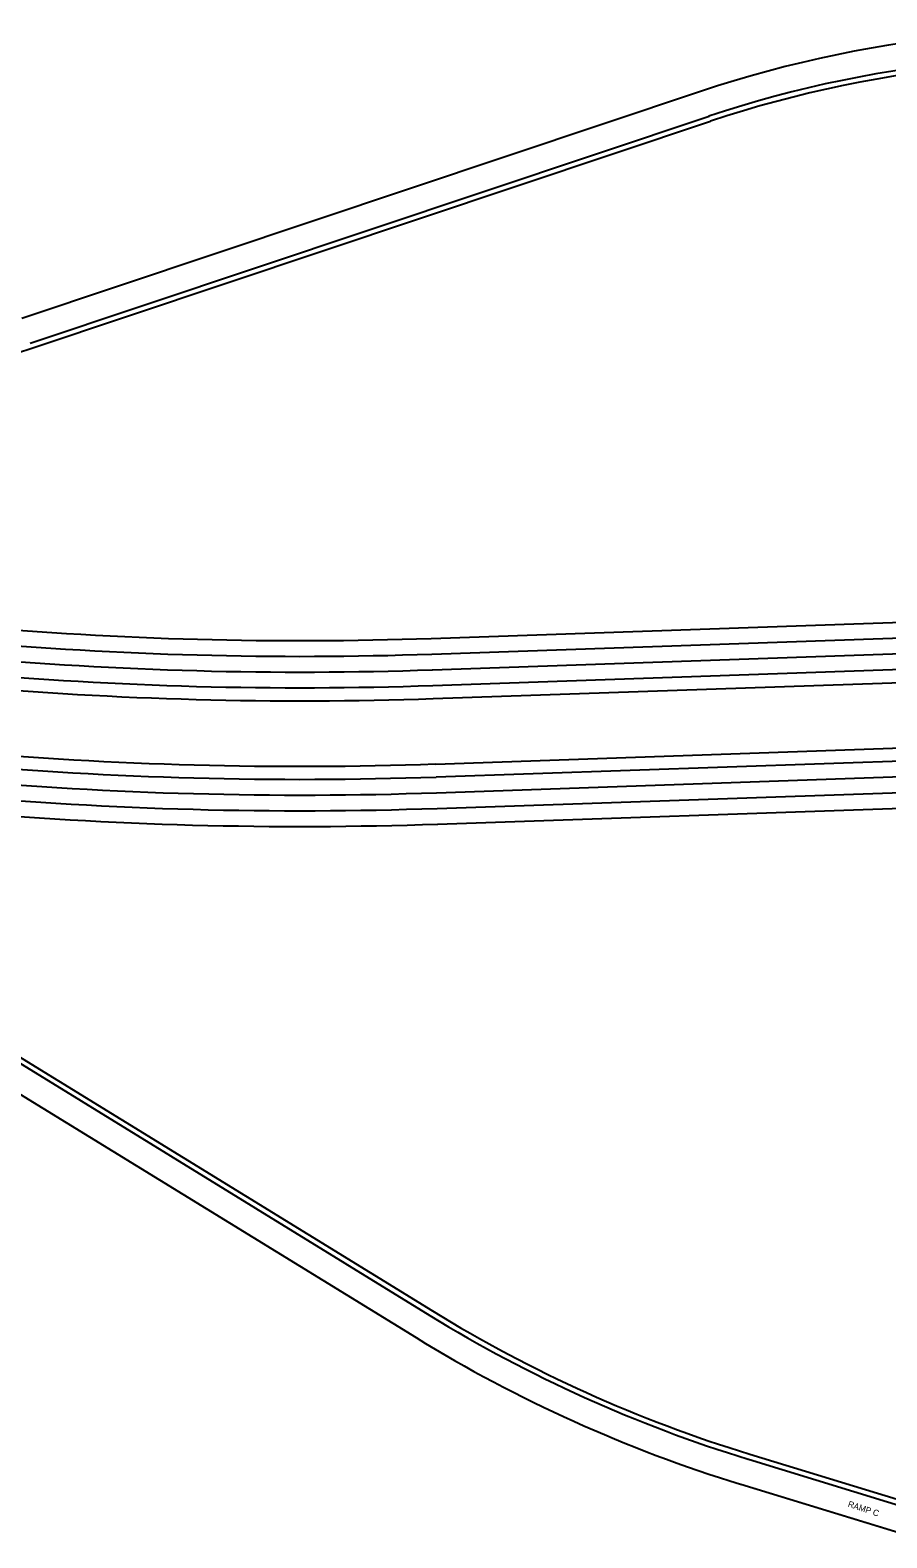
# Model space of a CAD drawing. Extents: x 2315515 to 2326910, y 758186 to 762794.
# Drawn here: x 2319969 to 2320623, y 759595 to 760747 of the extents above; entities that cross this region are included whole.
import ezdxf

# ---------------------------------------------------------------- set-up
doc = ezdxf.new("R2010")
doc.units = 0
for name, color, linetype in [('_CIVIL_CONSTRUCTION', 7, 'Continuous'), ('Default', 7, 'Continuous'), ('Draft_Corr_Design', 7, 'Continuous'), ('Draft_Corr_Range_Design', 7, 'Continuous'), ('E_Terrain_Exterior', 7, 'Continuous'), ('TL_Base Extension Sub', 7, 'Continuous'), ('TL_Pavement Centerline', 7, 'Continuous'), ('TL_Pavement Centerline Sub', 7, 'Continuous')]:
    doc.layers.add(name, color=color, linetype=linetype)

msp = doc.modelspace()

# ---------------------------------------------------------------- linework, layer by layer
at = {"layer": '_CIVIL_CONSTRUCTION'}
for p, q in [((2320276.5, 760246.3), (2324006, 760375.3)), ((2320278.9, 760176.4), (2324008.4, 760305.3))]:
    msp.add_line(p, q, dxfattribs=at)
for radius in [2931, 3001]:
    msp.add_arc((2320175.2, 763175.6), radius, 264.9144, 271.9805, dxfattribs=at)
at = {"layer": 'Draft_Corr_Design'}
for p, q in [((2320276.8, 760236.3), (2324006.3, 760365.3)), ((2320278.5, 760186.3), (2324008.1, 760315.3))]:
    msp.add_line(p, q, dxfattribs=at)
for radius in [2941, 2991]:
    msp.add_arc((2320175.2, 763175.6), radius, 264.9144, 271.9805, dxfattribs=at)
at = {"layer": 'Draft_Corr_Range_Design'}
for p, q in [((2320276.1, 760258.3), (2324005.6, 760387.3)), ((2320279.3, 760164.4), (2324008.8, 760293.3))]:
    msp.add_line(p, q, dxfattribs=at)
for radius in [2919, 3013]:
    msp.add_arc((2320175.2, 763175.6), radius, 264.9144, 271.9805, dxfattribs=at)
at = {"layer": 'E_Terrain_Exterior'}
for p, q in [((2319968.8, 760508), (2320487.5, 760681.4)), ((2319968.8, 760508), (2320487.5, 760681.4)), ((2319848.5, 760026.7), (2320274.1, 759765)), ((2320517.6, 759655.1), (2320668.3, 759608.9))]:
    msp.add_line(p, q, dxfattribs=at)
for centre, radius, start, end in [((2320768.6, 759840.1), 887, 81.2923, 108.4803), ((2320768.6, 759840.1), 887, 81.2923, 108.4803), ((2320826.1, 760662.9), 1054, 238.4184, 252.9768)]:
    msp.add_arc(centre, radius, start, end, dxfattribs=at)
at = {"layer": 'TL_Base Extension Sub'}
for p, q in [((2320275.6, 760270.3), (2322857, 760359.6)), ((2320279.7, 760152.4), (2322571.6, 760231.6))]:
    msp.add_line(p, q, dxfattribs=at)
for radius in [2907, 3025]:
    msp.add_arc((2320175.2, 763175.6), radius, 264.9144, 271.9805, dxfattribs=at)
at = {"layer": 'TL_Pavement Centerline'}
for p, q in [((2319962.4, 760527), (2320481.1, 760700.4)), ((2319962.4, 760527), (2320481.1, 760700.4)), ((2319970, 760504.2), (2320488.7, 760677.6)), ((2319850.6, 760030.1), (2320276.2, 759768.4)), ((2319838, 760009.6), (2320263.7, 759748)), ((2319838, 760009.6), (2320263.7, 759748)), ((2320518.7, 759658.9), (2320669.5, 759612.8)), ((2320511.7, 759636), (2320638.4, 759597.2)), ((2320511.7, 759636), (2320645.7, 759595))]:
    msp.add_line(p, q, dxfattribs=at)
for centre, radius, start, end in [((2320768.6, 759840.1), 907, 81.2923, 108.4803), ((2320768.6, 759840.1), 907, 81.2923, 108.4803), ((2320768.6, 759840.1), 883, 81.2923, 108.4803), ((2319073, 763188.3), 2830, 273.5389, 288.4803), ((2320826.1, 760662.9), 1050, 238.4184, 252.9768), ((2320826.1, 760662.9), 1074, 238.4184, 252.9768), ((2320826.1, 760662.9), 1074, 238.4184, 252.9768)]:
    msp.add_arc(centre, radius, start, end, dxfattribs=at)
at = {"layer": 'TL_Pavement Centerline Sub'}
for p, q in [((2320275.2, 760282.3), (2322856.6, 760371.6)), ((2320280.1, 760140.4), (2322560.1, 760219.2))]:
    msp.add_line(p, q, dxfattribs=at)
for radius in [2895, 3037]:
    msp.add_arc((2320175.2, 763175.6), radius, 264.9144, 271.9805, dxfattribs=at)

# ---------------------------------------------------------------- texts
at = {"layer": 'Default'}
msp.add_text('RAMP C', height=4.72, rotation=341.6007, dxfattribs=at).set_placement((2320593.2, 759618.9))

doc.saveas('drawing.dxf')
